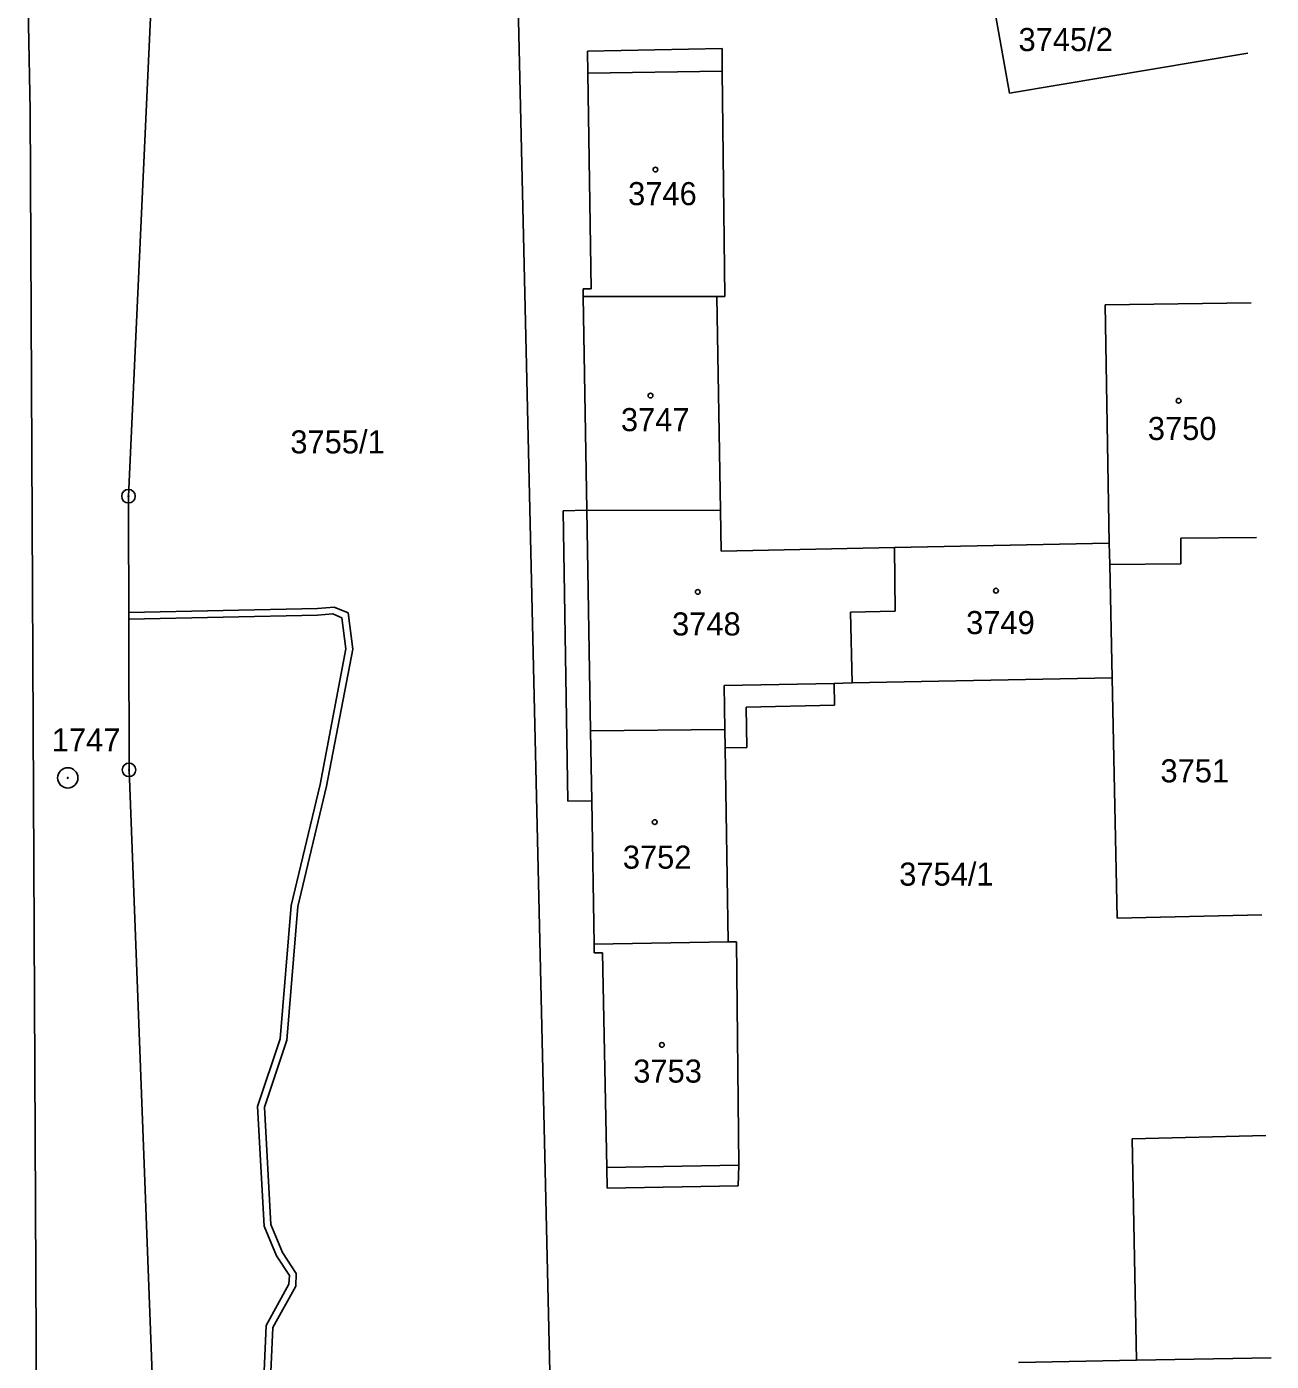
# Model space of a CAD drawing. Extents: x -735092 to -733385, y -1122435 to -1118992.
# Drawn here: x -734372.6 to -734280.8, y -1120680.1 to -1120581.8 of the extents above; entities that cross this region are included whole.
import ezdxf

# ---------------------------------------------------------------- set-up
doc = ezdxf.new("R2010")
doc.units = 0
for name, color, linetype in [('Vrstva 1', 7, 'Continuous'), ('Vrstva 10', 7, 'Continuous'), ('Vrstva 17', 7, 'Continuous'), ('Vrstva 18', 7, 'Continuous'), ('Vrstva 19', 7, 'Continuous'), ('Vrstva 25', 7, 'Continuous'), ('Vrstva 27', 7, 'Continuous'), ('Vrstva 4', 7, 'Continuous')]:
    doc.layers.add(name, color=color, linetype=linetype)

msp = doc.modelspace()

# ---------------------------------------------------------------- linework, layer by layer
at = {"layer": 'Vrstva 1'}
for points in [[(-734337.31, -1120538.94), (-734333.76, -1120691.49)], [(-734365.06, -1120616.4), (-734361.87, -1120546.92)], [(-734301.92, -1120576.65), (-734300.14, -1120586.71)], [(-734331.24, -1120583.61), (-734321.32, -1120583.43)], [(-734331.24, -1120583.61), (-734331.21, -1120585.23)], [(-734321.32, -1120583.43), (-734321.3, -1120585.09)], [(-734300.14, -1120586.71), (-734282.56, -1120583.77)], [(-734331.21, -1120585.23), (-734330.95, -1120601.12)], [(-734321.3, -1120585.09), (-734321.1, -1120601.69)], [(-734331.55, -1120601.13), (-734330.95, -1120601.12)], [(-734331.55, -1120601.13), (-734331.54, -1120601.69)], [(-734331.54, -1120601.69), (-734331.28, -1120617.43)], [(-734331.54, -1120601.69), (-734321.7, -1120601.7)], [(-734321.7, -1120601.7), (-734321.1, -1120601.69)], [(-734321.7, -1120601.7), (-734321.44, -1120617.46)], [(-734293.09, -1120602.31), (-734282.33, -1120602.15)], [(-734293.09, -1120602.31), (-734292.79, -1120619.86)], [(-734365.06, -1120616.4), (-734365.02, -1120636.56)], [(-734333.02, -1120617.48), (-734331.28, -1120617.43)], [(-734333.02, -1120617.48), (-734332.69, -1120638.87)], [(-734331.28, -1120617.43), (-734321.44, -1120617.46)], [(-734321.44, -1120617.46), (-734321.39, -1120620.46)], [(-734287.5, -1120619.5), (-734281.93, -1120619.43)], [(-734287.5, -1120621.37), (-734287.5, -1120619.5)], [(-734321.39, -1120620.46), (-734308.61, -1120620.19)], [(-734308.61, -1120620.19), (-734292.79, -1120619.86)], [(-734308.61, -1120620.19), (-734308.55, -1120624.86)], [(-734292.79, -1120619.86), (-734292.74, -1120621.43)], [(-734292.74, -1120621.43), (-734287.5, -1120621.37)], [(-734292.74, -1120621.43), (-734292.57, -1120629.79)], [(-734311.85, -1120624.95), (-734308.55, -1120624.86)], [(-734311.85, -1120624.95), (-734311.73, -1120630.14)], [(-734313.06, -1120630.19), (-734311.73, -1120630.14)], [(-734313.06, -1120630.19), (-734313.02, -1120631.8)], [(-734311.73, -1120630.14), (-734292.57, -1120629.79)], [(-734292.57, -1120629.79), (-734292.19, -1120647.48)], [(-734319.55, -1120631.93), (-734313.02, -1120631.8)], [(-734319.55, -1120631.93), (-734319.49, -1120634.91)], [(-734331, -1120633.69), (-734321.12, -1120633.58)], [(-734331, -1120633.69), (-734330.92, -1120638.84)], [(-734321.12, -1120633.58), (-734321.09, -1120634.94)], [(-734321.09, -1120634.94), (-734319.49, -1120634.91)], [(-734321.09, -1120634.94), (-734320.86, -1120649.24)], [(-734365.02, -1120636.56), (-734362.89, -1120692.04)], [(-734332.69, -1120638.87), (-734330.92, -1120638.84)], [(-734330.92, -1120638.84), (-734330.74, -1120649.39)], [(-734292.19, -1120647.48), (-734281.55, -1120647.25)], [(-734330.74, -1120649.39), (-734320.86, -1120649.24)], [(-734320.86, -1120649.24), (-734320.26, -1120649.23)], [(-734320.26, -1120649.23), (-734320.08, -1120665.67)], [(-734330.74, -1120649.39), (-734330.73, -1120650.04)], [(-734330.73, -1120650.04), (-734330.13, -1120650.03)], [(-734330.13, -1120650.03), (-734329.81, -1120665.85)], [(-734291.1, -1120663.75), (-734281.24, -1120663.49)], [(-734291.1, -1120663.75), (-734290.77, -1120680.04)], [(-734329.81, -1120665.85), (-734329.78, -1120667.37)], [(-734320.14, -1120667.2), (-734320.08, -1120665.67)], [(-734329.78, -1120667.37), (-734320.14, -1120667.2)], [(-734299.47, -1120680.22), (-734290.77, -1120680.04)]]:
    msp.add_lwpolyline(points, dxfattribs=at)
at = {"layer": 'Vrstva 10'}
for points in [[(-734372.56, -1120575.37), (-734372.31, -1120587.96)], [(-734372.31, -1120587.96), (-734371.18, -1120819.86)]]:
    msp.add_lwpolyline(points, dxfattribs=at)
at = {"layer": 'Vrstva 25'}
for centre, radius in [((-734326.23, -1120592.34), 0.175), ((-734326.59, -1120608.99), 0.175), ((-734287.67, -1120609.37), 0.175), ((-734365.06, -1120616.4), 0.5), ((-734365.06, -1120616.4), 0.032), ((-734323.11, -1120623.45), 0.175), ((-734301.13, -1120623.36), 0.175), ((-734369.53, -1120637.15), 0.75), ((-734365.02, -1120636.56), 0.5), ((-734369.53, -1120637.15), 0.032), ((-734365.02, -1120636.56), 0.032), ((-734326.28, -1120640.41), 0.175), ((-734325.75, -1120656.82), 0.175)]:
    msp.add_circle(centre, radius, dxfattribs=at)
at = {"layer": 'Vrstva 27'}
for points in [[(-734365.04, -1120624.96), (-734351.14, -1120624.67), (-734349.91, -1120624.57), (-734348.88, -1120625), (-734348.53, -1120627.66), (-734350.46, -1120637.75), (-734352.57, -1120646.63), (-734353.38, -1120656.47), (-734355.04, -1120661.41), (-734354.56, -1120670.05), (-734353.7, -1120672.12), (-734352.7, -1120673.67), (-734352.73, -1120674.59), (-734354.41, -1120677.63), (-734354.56, -1120680.91)], [(-734365.04, -1120625.46), (-734365.04, -1120624.96)], [(-734355.06, -1120680.85), (-734354.91, -1120677.49), (-734353.23, -1120674.45), (-734353.2, -1120673.81), (-734354.14, -1120672.36), (-734355.06, -1120670.17), (-734355.54, -1120661.35), (-734353.88, -1120656.37), (-734353.07, -1120646.55), (-734350.94, -1120637.65), (-734349.03, -1120627.64), (-734349.34, -1120625.35), (-734349.99, -1120625.07), (-734351.12, -1120625.17), (-734365.04, -1120625.46)]]:
    msp.add_lwpolyline(points, dxfattribs=at)
at = {"layer": 'Vrstva 4'}
for points in [[(-734331.21, -1120585.23), (-734321.3, -1120585.09)], [(-734331.28, -1120617.43), (-734331, -1120633.69)], [(-734321.17, -1120630.35), (-734313.06, -1120630.19)], [(-734321.17, -1120630.35), (-734321.12, -1120633.58)], [(-734329.81, -1120665.85), (-734320.08, -1120665.67)], [(-734290.77, -1120680.04), (-734280.84, -1120679.87)]]:
    msp.add_lwpolyline(points, dxfattribs=at)

# ---------------------------------------------------------------- texts
at = {"layer": 'Vrstva 17'}
msp.add_text('1747', height=1.7, dxfattribs=at).set_placement((-734370.71, -1120635.2))
at = {"layer": 'Vrstva 18'}
for s, p in [('3745/2', (-734299.47, -1120583.61)), ('3755/1', (-734353.13, -1120613.25)), ('3754/1', (-734308.26, -1120645.09))]:
    msp.add_text(s, height=1.7, dxfattribs=at).set_placement(p)
at = {"layer": 'Vrstva 19'}
for s, p in [('3746', (-734328.24, -1120594.96)), ('3747', (-734328.77, -1120611.61)), ('3750', (-734289.94, -1120612.26)), ('3748', (-734325, -1120626.66)), ('3749', (-734303.33, -1120626.56)), ('3751', (-734289.01, -1120637.48)), ('3752', (-734328.63, -1120643.84)), ('3753', (-734327.86, -1120659.6))]:
    msp.add_text(s, height=1.7, dxfattribs=at).set_placement(p)

doc.saveas('drawing.dxf')
